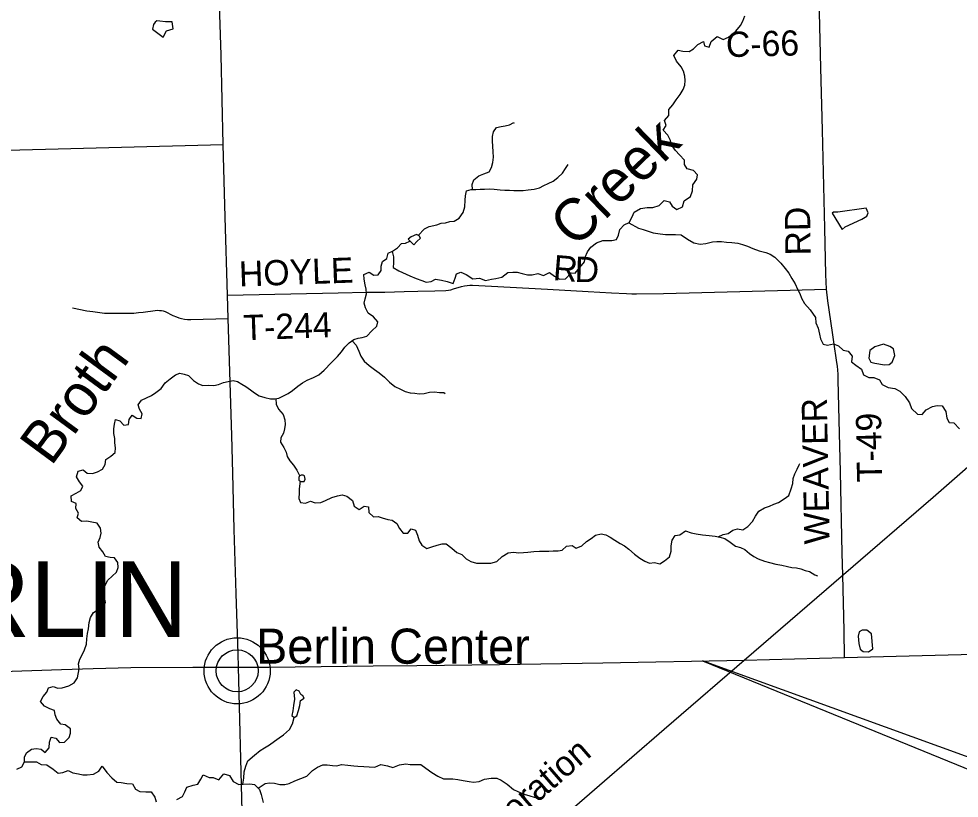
# Model space of a CAD drawing. Extents: x 0 to 34, y 0 to 22.
# Drawn here: x 4.591 to 6.707, y 17.274 to 19.028 of the extents above; entities that cross this region are included whole.
import ezdxf

# ---------------------------------------------------------------- set-up
doc = ezdxf.new("R2010")
doc.units = 0
for name, color, linetype in [('GM_X_County_Road_Text', 7, 'Continuous'), ('GM_X_Minor_Lake', 7, 'Continuous'), ('GM_X_Minor_River', 7, 'Continuous'), ('GM_X_Minor_River_Text', 7, 'Continuous'), ('GM_X_Rail_Line', 7, 'Continuous'), ('GM_X_Rail_Line_Text', 7, 'Continuous'), ('GM_X_State_Route', 7, 'Continuous'), ('GM_X_Township_Road', 7, 'Continuous'), ('GM_X_Township_Road_Text', 7, 'Continuous'), ('GM_X_Township_Text', 7, 'Continuous'), ('GM_X_Unincorporated', 7, 'Continuous'), ('GM_X_Unincorporated_Location', 7, 'Continuous'), ('GM_X_Unincorporated_Text', 7, 'Continuous'), ('GM_X_US_Route', 7, 'Continuous'), ('SH_Text', 7, 'Continuous')]:
    doc.layers.add(name, color=color, linetype=linetype)

msp = doc.modelspace()

# ---------------------------------------------------------------- linework, layer by layer
at = {"layer": 'GM_X_Minor_Lake'}
for points in [[(4.9357, 19.0214), (4.9205, 19.0217), (4.9076, 19.0231), (4.9015, 19.0234), (4.8973, 19.0204), (4.894, 19.0158), (4.8914, 19.0051), (4.9151, 18.9871), (4.923, 19.0016), (4.9382, 19.0059)], [(4.9382, 19.0059), (4.9357, 19.0214)], [(6.4435, 18.554), (6.4499, 18.5598), (6.4877, 18.5773), (6.499, 18.5843), (6.5016, 18.5916), (6.4977, 18.6018), (6.4335, 18.593), (6.424, 18.5933), (6.4206, 18.5909)], [(6.4206, 18.5909), (6.4435, 18.554)], [(5.4792, 18.5196), (5.486, 18.5269), (5.4943, 18.5345), (5.4915, 18.5394), (5.4854, 18.5428), (5.4737, 18.5374), (5.4669, 18.532)], [(5.4669, 18.532), (5.4792, 18.5196)], [(6.5385, 18.249), (6.5495, 18.2503), (6.5559, 18.2553), (6.5622, 18.2706), (6.5593, 18.285), (6.5509, 18.2906), (6.5364, 18.2958), (6.5167, 18.2898), (6.5058, 18.2817), (6.5033, 18.2642), (6.5076, 18.2555), (6.5168, 18.2529)], [(6.5168, 18.2529), (6.5385, 18.249)], [(5.2316, 18.0002), (5.2302, 18.001), (5.2299, 18.001), (5.2278, 18.001), (5.2256, 18.0009), (5.2233, 17.9998), (5.2216, 17.9979), (5.2207, 17.9957), (5.2205, 17.9932), (5.2206, 17.9898)], [(5.2206, 17.9898), (5.2252, 17.9865), (5.2325, 17.9869), (5.2351, 17.9922), (5.2335, 17.9991), (5.2316, 18.0002)], [(6.5097, 17.6441), (6.499, 17.6519), (6.4887, 17.6522), (6.4815, 17.6479), (6.4794, 17.6384), (6.4807, 17.622), (6.4839, 17.6095), (6.4905, 17.6039), (6.5027, 17.6029), (6.5128, 17.6099)], [(6.5128, 17.6099), (6.5097, 17.6441)], [(5.2053, 17.4597), (5.21, 17.4557), (5.2163, 17.4589), (5.2202, 17.4715), (5.223, 17.4822), (5.2243, 17.4937), (5.2325, 17.4992), (5.2297, 17.5044), (5.2251, 17.5074), (5.2215, 17.5149), (5.215, 17.5174), (5.2098, 17.5123), (5.2109, 17.4964), (5.2089, 17.4826), (5.2073, 17.4701)], [(5.2073, 17.4701), (5.2053, 17.4597)]]:
    msp.add_lwpolyline(points, dxfattribs=at)
at = {"layer": 'GM_X_Minor_River'}
for points in [[(6.134, 18.9673), (6.144, 18.9645), (6.149, 18.9776), (6.162, 18.9885), (6.1759, 18.982), (6.1879, 18.9872), (6.204, 19.0005), (6.2147, 19.0133), (6.2202, 19.0229), (6.2245, 19.0348)], [(5.4311, 18.5048), (5.4338, 18.4928), (5.4337, 18.4791), (5.4332, 18.4688), (5.4459, 18.4611), (5.4705, 18.4495), (5.4844, 18.4438), (5.4974, 18.4391), (5.5074, 18.4356), (5.5184, 18.4366), (5.5285, 18.4425), (5.5415, 18.4402), (5.5545, 18.4371), (5.5679, 18.4321), (5.5722, 18.4443), (5.5754, 18.4539), (5.5852, 18.4576), (5.5971, 18.4525), (5.6122, 18.443), (5.6274, 18.4445), (5.6408, 18.4395), (5.6541, 18.4424), (5.6639, 18.4438), (5.6779, 18.4464), (5.691, 18.4574), (5.7024, 18.458), (5.7119, 18.4579), (5.723, 18.4551), (5.7352, 18.452), (5.7455, 18.4522), (5.7584, 18.4552), (5.7714, 18.4505), (5.7846, 18.4569), (5.7962, 18.4492), (5.8081, 18.4419), (5.821, 18.4433), (5.8333, 18.4562), (5.8428, 18.456), (5.8532, 18.4684), (5.8639, 18.4812), (5.8648, 18.4915), (5.8706, 18.5038), (5.878, 18.5142), (5.8907, 18.5237), (5.9046, 18.5289), (5.9149, 18.5292), (5.9248, 18.529), (5.9354, 18.5312), (5.9401, 18.5415), (5.9428, 18.5542), (5.9525, 18.5646), (5.9642, 18.5695), (5.9707, 18.5822), (5.9754, 18.5929), (5.9893, 18.6016), (6.0048, 18.6039), (6.0177, 18.6038), (6.0317, 18.6083), (6.0429, 18.6192), (6.0551, 18.6161), (6.0607, 18.6063), (6.0715, 18.599), (6.0843, 18.6054), (6.0881, 18.6188), (6.1024, 18.6282), (6.107, 18.6413), (6.1071, 18.6546), (6.1167, 18.6673), (6.1176, 18.6769), (6.109, 18.6869), (6.0948, 18.6904), (6.0889, 18.7005), (6.0883, 18.71), (6.077, 18.7219), (6.0684, 18.7316), (6.0593, 18.7443), (6.0572, 18.7545), (6.0508, 18.7662), (6.0403, 18.7773), (6.0477, 18.7881), (6.0436, 18.7994), (6.0536, 18.8103), (6.0537, 18.8244), (6.0622, 18.8349), (6.0699, 18.8457), (6.0788, 18.8577), (6.0857, 18.8692), (6.0893, 18.8792), (6.0902, 18.8891), (6.0892, 18.899), (6.0863, 18.9103), (6.0811, 18.9205), (6.0709, 18.9328), (6.0649, 18.9455), (6.0741, 18.9576), (6.0852, 18.9555), (6.0989, 18.9547), (6.1091, 18.961), (6.1187, 18.9708), (6.1315, 18.9775), (6.134, 18.9673)], [(5.6117, 18.644), (5.6111, 18.6552), (5.6144, 18.6655), (5.6261, 18.6751), (5.6371, 18.679), (5.6489, 18.6837), (5.6545, 18.6936), (5.6574, 18.705), (5.6589, 18.7168), (5.658, 18.7286), (5.6575, 18.7415), (5.6566, 18.7525), (5.6562, 18.7632), (5.6587, 18.7738), (5.6655, 18.7834), (5.6757, 18.7858), (5.6852, 18.7874), (5.6947, 18.7897), (5.7046, 18.7947), (5.7053, 18.7936)], [(5.4892, 18.5408), (5.5032, 18.5555), (5.5142, 18.5605), (5.5313, 18.5645), (5.5407, 18.568), (5.551, 18.5692), (5.5605, 18.5719), (5.57, 18.5728), (5.5813, 18.5793), (5.5907, 18.592), (5.5944, 18.6053), (5.5947, 18.6197), (5.5961, 18.6296), (5.5983, 18.6411), (5.6082, 18.6438), (5.6188, 18.6443), (5.6291, 18.6447), (5.6386, 18.6448), (5.6492, 18.6453), (5.6603, 18.6446), (5.6736, 18.6432), (5.6846, 18.6429), (5.6949, 18.6422), (5.7048, 18.6419), (5.7154, 18.642), (5.7257, 18.6417), (5.7367, 18.6433), (5.75, 18.6446), (5.7622, 18.6481), (5.772, 18.6528), (5.7819, 18.6574), (5.7928, 18.6628), (5.8038, 18.6709), (5.8144, 18.6808), (5.8211, 18.6912), (5.8267, 18.7)], [(5.9632, 18.5691), (5.9854, 18.5571), (5.9953, 18.5539), (6.0065, 18.5499), (6.0183, 18.5464), (6.0336, 18.5441), (6.0458, 18.5429), (6.0584, 18.5428), (6.0682, 18.543), (6.0812, 18.5422), (6.0955, 18.5323), (6.1094, 18.5242), (6.1239, 18.5211), (6.1368, 18.5222), (6.1516, 18.5264), (6.1614, 18.5273), (6.1717, 18.5272), (6.1828, 18.5256), (6.195, 18.5251), (6.2087, 18.5231), (6.2194, 18.5203), (6.2301, 18.5168), (6.2424, 18.5114), (6.257, 18.506), (6.2716, 18.5022), (6.2812, 18.4982), (6.292, 18.492), (6.3056, 18.4783), (6.315, 18.4663), (6.3232, 18.4555), (6.3304, 18.4439), (6.3375, 18.4315), (6.3431, 18.4194), (6.3479, 18.4097), (6.3523, 18.3995), (6.3587, 18.3871), (6.3716, 18.3734), (6.3834, 18.3558), (6.3844, 18.3436), (6.3893, 18.3316), (6.3926, 18.3187), (6.3944, 18.3081), (6.4008, 18.2957), (6.4107, 18.2933), (6.424, 18.2966), (6.4355, 18.292), (6.446, 18.2823), (6.4567, 18.2799), (6.4661, 18.2687), (6.4641, 18.2561), (6.4742, 18.2484), (6.4869, 18.2396), (6.4918, 18.2268), (6.5037, 18.2206), (6.5144, 18.2212), (6.5274, 18.2154), (6.5338, 18.2049), (6.5472, 18.1984), (6.5621, 18.1957), (6.5729, 18.1899), (6.5854, 18.178), (6.5948, 18.1638), (6.5997, 18.1513), (6.6129, 18.138), (6.6232, 18.1378), (6.6325, 18.1479), (6.6464, 18.1555), (6.6573, 18.158), (6.6684, 18.1571), (6.6767, 18.1444), (6.6789, 18.1296), (6.6841, 18.1199), (6.6948, 18.1186), (6.7073, 18.1056)], [(5.0293, 18.203), (5.04, 18.205), (5.051, 18.2093), (5.062, 18.212), (5.0726, 18.214), (5.0825, 18.2118), (5.0921, 18.2055), (5.1016, 18.2006), (5.1116, 18.1927), (5.1212, 18.1863), (5.1315, 18.1796), (5.1441, 18.1755), (5.1566, 18.1725), (5.1665, 18.1726), (5.176, 18.1742), (5.1965, 18.1846), (5.2063, 18.1912), (5.2188, 18.2012), (5.229, 18.2085), (5.2396, 18.215), (5.254, 18.2209), (5.2657, 18.227), (5.2778, 18.237), (5.2944, 18.2543), (5.3076, 18.2684), (5.3166, 18.2788), (5.3245, 18.2891), (5.3343, 18.2987), (5.3441, 18.3064), (5.354, 18.3095), (5.3635, 18.3111), (5.3737, 18.3142), (5.385, 18.3261), (5.3964, 18.3364), (5.3982, 18.3463), (5.3886, 18.3573), (5.3771, 18.3656), (5.3709, 18.3777), (5.3677, 18.3879), (5.3699, 18.3978), (5.3729, 18.4092), (5.3724, 18.4195), (5.3697, 18.4297), (5.3676, 18.4423), (5.3672, 18.4525), (5.3793, 18.4576), (5.3892, 18.4512), (5.3991, 18.452), (5.4059, 18.4616), (5.4058, 18.4711), (5.4088, 18.4817), (5.419, 18.4891), (5.4219, 18.5005), (5.4318, 18.5051), (5.4427, 18.5124), (5.4514, 18.5224), (5.4609, 18.5232), (5.4708, 18.5281)], [(5.3404, 18.3035), (5.3499, 18.2935), (5.3554, 18.2798), (5.3604, 18.2692), (5.3681, 18.2579), (5.3793, 18.2481), (5.3907, 18.2391), (5.4018, 18.2316), (5.4133, 18.2214), (5.4249, 18.2105), (5.4364, 18.2003), (5.4497, 18.1943), (5.4597, 18.1895), (5.4715, 18.1865), (5.4814, 18.1859), (5.4913, 18.184), (5.5031, 18.1845), (5.5148, 18.188), (5.5258, 18.1885), (5.5369, 18.1871), (5.5472, 18.1872), (5.5502, 18.1849)], [(4.6481, 17.4811), (4.6397, 17.4913), (4.6457, 17.5024), (4.6536, 17.5123), (4.6577, 17.5222), (4.6675, 17.525), (4.6786, 17.5217), (4.6881, 17.5221), (4.7029, 17.5268), (4.7154, 17.5334), (4.7229, 17.5444), (4.7265, 17.565), (4.7249, 17.576), (4.7278, 17.5871), (4.7338, 17.5981), (4.7383, 17.608), (4.7431, 17.6206), (4.7438, 17.6324), (4.7452, 17.6446), (4.747, 17.6553), (4.7492, 17.669), (4.7521, 17.6804), (4.7589, 17.6915), (4.7691, 17.6988), (4.7797, 17.7034), (4.7857, 17.7145), (4.7837, 17.7263), (4.7809, 17.7392), (4.7846, 17.7532), (4.7909, 17.7647), (4.8007, 17.7739), (4.8105, 17.7823), (4.8139, 17.7934), (4.8134, 17.804), (4.8057, 17.8146), (4.7962, 17.8157), (4.7859, 17.8179), (4.7793, 17.8281), (4.7716, 17.8387), (4.7689, 17.8501), (4.7733, 17.8604), (4.7755, 17.8703), (4.7743, 17.882), (4.767, 17.8926), (4.7548, 17.8952), (4.7434, 17.8974), (4.7319, 17.8965), (4.722, 17.9048), (4.7249, 17.9151), (4.7191, 17.9257), (4.7198, 17.9371), (4.7091, 17.9416), (4.7082, 17.9545), (4.7196, 17.9603), (4.7298, 17.9664), (4.7343, 17.9764), (4.7274, 17.9862), (4.7204, 17.9975), (4.7241, 18.0101), (4.7351, 18.0132), (4.7447, 18.0053), (4.7561, 18.005), (4.7675, 18.0086), (4.7785, 18.0147), (4.7852, 18.025), (4.7866, 18.0361), (4.7976, 18.0434), (4.8074, 18.0518), (4.8081, 18.0625), (4.8068, 18.0739), (4.8064, 18.0834), (4.804, 18.0944), (4.8043, 18.1054), (4.8061, 18.1161), (4.8079, 18.126), (4.8178, 18.1234), (4.8266, 18.1136), (4.8373, 18.1148), (4.8387, 18.1262), (4.8458, 18.1362), (4.8562, 18.1294), (4.8657, 18.1287), (4.8683, 18.1394), (4.8625, 18.1492), (4.8589, 18.1594), (4.8665, 18.1698), (4.8778, 18.1752), (4.8888, 18.1806), (4.899, 18.1871), (4.9111, 18.1964), (4.9201, 18.2086), (4.9311, 18.2178), (4.9432, 18.227), (4.953, 18.2305), (4.9629, 18.2287), (4.9725, 18.225), (4.984, 18.2144), (4.9951, 18.2069), (5.005, 18.2025), (5.0175, 18.2033), (5.0293, 18.203)], [(5.1687, 18.173), (5.1697, 18.1605), (5.1747, 18.1495), (5.1855, 18.1374), (5.189, 18.1253), (5.1899, 18.115), (5.1884, 18.1055), (5.1862, 18.0952), (5.1802, 18.0849), (5.1796, 18.075), (5.1869, 18.0629), (5.1919, 18.0531), (5.1943, 18.0432), (5.2001, 18.033), (5.2086, 18.0232), (5.2159, 18.0122), (5.2217, 18.002), (5.2234, 17.9998)], [(6.1647, 17.8621), (6.1757, 17.8674), (6.1867, 17.8698), (6.1973, 17.8774), (6.2079, 17.8798), (6.2197, 17.8776), (6.2314, 17.8857), (6.2416, 17.8968), (6.2487, 17.909), (6.2559, 17.9201), (6.2687, 17.9271), (6.2797, 17.9313), (6.29, 17.9356), (6.2998, 17.9395), (6.3127, 17.9479), (6.3233, 17.9549), (6.3285, 17.9701), (6.3322, 17.9823), (6.3328, 17.9933), (6.3369, 18.0036), (6.3418, 18.0143), (6.347, 18.0242), (6.3485, 18.0269)], [(5.2237, 17.9876), (5.2216, 17.9705), (5.2217, 17.961), (5.221, 17.9488), (5.2241, 17.9393), (5.2359, 17.9379), (5.2469, 17.9425), (5.2576, 17.9388), (5.2702, 17.9393), (5.2804, 17.944), (5.2948, 17.9505), (5.3077, 17.9548), (5.3183, 17.9564), (5.3286, 17.9539), (5.3412, 17.9437), (5.3452, 17.9312), (5.3563, 17.9237), (5.3676, 17.9314), (5.3775, 17.9299), (5.3784, 17.9166), (5.3891, 17.9072), (5.399, 17.9077), (5.4085, 17.9051), (5.4207, 17.901), (5.431, 17.9), (5.441, 17.8925), (5.4472, 17.8811), (5.4552, 17.8701), (5.4659, 17.8706), (5.4734, 17.8802), (5.483, 17.8768), (5.488, 17.8662), (5.4915, 17.853), (5.4977, 17.8431), (5.5088, 17.836), (5.5198, 17.8395), (5.5323, 17.8434), (5.5429, 17.8462), (5.5524, 17.8466), (5.5647, 17.8365), (5.5766, 17.8271), (5.5873, 17.8222), (5.5973, 17.8124), (5.608, 17.8064), (5.6205, 17.8027), (5.6308, 17.8028), (5.6415, 17.8025), (5.6525, 17.803), (5.6661, 17.8069), (5.6786, 17.818), (5.6915, 17.8261), (5.704, 17.8277), (5.7158, 17.8263), (5.7265, 17.8272), (5.736, 17.8273), (5.7493, 17.8289), (5.7622, 17.8297), (5.7835, 17.8299), (5.7934, 17.8308), (5.804, 17.8309), (5.8135, 17.8321), (5.8233, 17.8409), (5.8355, 17.8429), (5.845, 17.8369), (5.8576, 17.8419), (5.8681, 17.8515), (5.8783, 17.8585), (5.8885, 17.8658), (5.9014, 17.8689), (5.9117, 17.8667), (5.9213, 17.8615), (5.9316, 17.8547), (5.9435, 17.8472), (5.9534, 17.842), (5.9637, 17.8345), (5.976, 17.8232), (5.9883, 17.8141), (5.9997, 17.807), (6.0097, 17.8025), (6.0214, 17.8045), (6.0329, 17.8016), (6.0435, 17.8081), (6.0548, 17.817), (6.0589, 17.8296), (6.0588, 17.8417), (6.0609, 17.855), (6.0673, 17.865), (6.0779, 17.8666), (6.0908, 17.8758), (6.1034, 17.8713), (6.1152, 17.8692), (6.1289, 17.8666), (6.1438, 17.8652), (6.1575, 17.8638), (6.1685, 17.8612), (6.1792, 17.8587), (6.1914, 17.85), (6.2033, 17.8414), (6.2148, 17.8381), (6.2243, 17.8336), (6.235, 17.8249)], [(6.235, 17.8249), (6.2446, 17.8182), (6.2545, 17.8129), (6.269, 17.8073), (6.2797, 17.804), (6.2938, 17.8007), (6.3079, 17.7985), (6.3205, 17.7952), (6.3304, 17.793), (6.3403, 17.7927), (6.3506, 17.7901), (6.3605, 17.7864), (6.37, 17.7842), (6.3823, 17.7767), (6.388, 17.7745)], [(4.5859, 17.3388), (4.5972, 17.3446), (4.6036, 17.3553), (4.6035, 17.3663), (4.608, 17.3759), (4.6189, 17.3839), (4.6296, 17.3859), (4.6406, 17.3841), (4.6502, 17.3766), (4.6589, 17.3869), (4.6595, 17.3999), (4.6636, 17.4109), (4.6735, 17.4091), (4.6819, 17.3993), (4.693, 17.4001), (4.7039, 17.4101), (4.7069, 17.42), (4.7068, 17.4299), (4.6949, 17.4389), (4.6854, 17.4407), (4.6762, 17.4513), (4.6727, 17.4612), (4.671, 17.4714), (4.6604, 17.4751), (4.6481, 17.4811)], [(5.0947, 17.3054), (5.0967, 17.3192), (5.0976, 17.3329), (5.1018, 17.3459), (5.1057, 17.3582), (5.121, 17.3707), (5.1337, 17.3809), (5.1435, 17.3872), (5.1547, 17.3939), (5.1656, 17.4022), (5.1768, 17.41), (5.1865, 17.4167), (5.1996, 17.4284), (5.2065, 17.4415), (5.21, 17.4557)], [(4.6036, 17.3553), (4.6307, 17.3558), (4.6411, 17.3496), (4.6537, 17.3491), (4.668, 17.3388), (4.6788, 17.3299), (4.6894, 17.3313), (4.7015, 17.3358), (4.7123, 17.3307), (4.7249, 17.3287), (4.7348, 17.3267), (4.7447, 17.3262), (4.7588, 17.3276), (4.7704, 17.3344), (4.7781, 17.3459), (4.7887, 17.3317), (4.7996, 17.3198), (4.8109, 17.3098), (4.8208, 17.3093), (4.8334, 17.3069), (4.8467, 17.3061), (4.8535, 17.2941), (4.8631, 17.2886), (4.8761, 17.2882), (4.8883, 17.2877), (4.8965, 17.2761), (4.8998, 17.2659)], [(5.1292, 17.2962), (5.1446, 17.3066), (5.1548, 17.308), (5.1662, 17.3079), (5.1777, 17.3047), (5.1891, 17.3046), (5.199, 17.3071), (5.2118, 17.3128), (5.2253, 17.3184), (5.2385, 17.3233), (5.2515, 17.3361), (5.2624, 17.3436), (5.2748, 17.3488), (5.2847, 17.3491), (5.2965, 17.3475), (5.3064, 17.3469), (5.317, 17.3495), (5.3311, 17.3479), (5.3441, 17.3467), (5.3536, 17.3458), (5.367, 17.3449), (5.3792, 17.3441), (5.3914, 17.3436), (5.4049, 17.3496), (5.4202, 17.3466), (5.4321, 17.3427), (5.4475, 17.3487), (5.4616, 17.351), (5.4715, 17.3497), (5.4844, 17.3496), (5.4954, 17.3499), (5.5063, 17.341), (5.5198, 17.3318), (5.5333, 17.323), (5.546, 17.3176), (5.5567, 17.3171), (5.5673, 17.3173), (5.5788, 17.3157), (5.5902, 17.3137), (5.604, 17.3117), (5.6139, 17.3101), (5.6264, 17.3115), (5.6385, 17.3164), (5.6536, 17.319), (5.6666, 17.3185), (5.6762, 17.3142), (5.6897, 17.305), (5.7037, 17.2932), (5.7137, 17.2885), (5.7275, 17.2831), (5.7402, 17.2788), (5.7501, 17.276), (5.7597, 17.2736)], [(4.9461, 17.2708), (4.9592, 17.2776), (4.9639, 17.2883), (4.9686, 17.2987), (4.983, 17.3032), (4.9936, 17.3054), (4.9998, 17.3165), (5.0057, 17.3262), (5.0187, 17.32), (5.0282, 17.3206), (5.0405, 17.3152), (5.0516, 17.3284), (5.065, 17.3249), (5.0726, 17.3114), (5.0857, 17.3049), (5.0955, 17.3055), (5.1104, 17.3062), (5.1207, 17.3049), (5.132, 17.2934), (5.1356, 17.2821), (5.1406, 17.2643)]]:
    msp.add_lwpolyline(points, dxfattribs=at)
at = {"layer": 'GM_X_Rail_Line'}
msp.add_lwpolyline([(5.8073, 17.2253), (5.8974, 17.3034), (6.0426, 17.4289), (6.6479, 17.9515), (6.8284, 18.1087)], dxfattribs=at)
at = {"layer": 'GM_X_State_Route'}
for points in [[(5.0719, 18.0057), (5.0696, 18.0902), (5.0619, 18.3533), (5.0598, 18.4059), (5.0552, 18.5818), (5.0505, 18.745), (5.0459, 18.9465), (5.0415, 19.0842)], [(5.0847, 17.5684), (5.0838, 17.599), (5.08, 17.7346), (5.0754, 17.8783), (5.0719, 18.0057)], [(5.1103, 16.5663), (5.1099, 16.5961), (5.0847, 17.5684)]]:
    msp.add_lwpolyline(points, dxfattribs=at)
at = {"layer": 'GM_X_Township_Road'}
for points in [[(6.408, 18.4195), (6.4068, 18.4524), (6.4043, 18.5569), (6.3989, 18.7778), (6.3954, 18.9178), (6.3926, 19.0426), (6.3876, 19.2294), (6.383, 19.4112), (6.3765, 19.6635)], [(3.0395, 18.6946), (3.3635, 18.7014), (5.0505, 18.745)], [(5.0598, 18.4059), (5.3093, 18.4114), (5.3732, 18.4126), (5.4146, 18.4133), (5.4575, 18.4145), (5.4885, 18.4153), (5.5269, 18.4157), (5.5518, 18.4168), (5.5573, 18.4174), (5.5626, 18.4185), (5.5687, 18.4202), (5.5871, 18.4255), (5.5933, 18.4271), (5.5999, 18.4281), (5.6058, 18.4286), (5.6117, 18.4286), (5.6542, 18.4262), (5.7801, 18.4195), (5.8721, 18.4145), (5.9241, 18.4116), (5.9584, 18.4098), (5.9698, 18.4093), (5.9807, 18.409), (6.0412, 18.4098), (6.1275, 18.4123), (6.3262, 18.4174), (6.408, 18.4195)], [(6.4485, 17.5907), (6.4476, 17.6514), (6.4448, 17.7758), (6.4435, 17.8256), (6.4395, 18.0087), (6.4369, 18.1246), (6.4347, 18.2157), (6.4343, 18.2281), (6.4336, 18.2375), (6.4327, 18.2463), (6.4315, 18.2547), (6.4299, 18.2652), (6.4264, 18.2906), (6.4218, 18.3224), (6.4114, 18.3931), (6.408, 18.4195)], [(4.711, 18.3774), (4.7438, 18.3712), (4.757, 18.3693), (4.7729, 18.3671), (4.7833, 18.366), (4.795, 18.3654), (4.8088, 18.3653), (4.838, 18.3653), (4.8494, 18.366), (4.8602, 18.3668), (4.8707, 18.368), (4.8975, 18.3717), (4.9031, 18.3721), (4.9073, 18.372), (4.9116, 18.3716), (4.9154, 18.3706), (4.9196, 18.3694), (4.9372, 18.3607), (4.9455, 18.3572), (4.9509, 18.3551), (4.957, 18.3534), (4.9636, 18.352), (4.9699, 18.3511), (4.9773, 18.3511), (5.0619, 18.3533)]]:
    msp.add_lwpolyline(points, dxfattribs=at)
at = {"layer": 'GM_X_Unincorporated'}
for radius in [0.0744, 0.0472]:
    msp.add_circle((5.0819, 17.5605), radius, dxfattribs=at)
at = {"layer": 'GM_X_Unincorporated_Location'}
msp.add_line((5.0819, 17.5605), (5.0819, 17.5605), dxfattribs=at)
at = {"layer": 'GM_X_US_Route'}
for points in [[(5.486, 17.5725), (5.6721, 17.5744), (5.9049, 17.5783), (6.2235, 17.5848), (6.4485, 17.5907), (7.1191, 17.6075), (7.1293, 17.6073), (7.1366, 17.6069), (7.1443, 17.6061), (7.1511, 17.6052), (7.158, 17.6037), (7.1656, 17.6022), (7.178, 17.5993), (7.2115, 17.5908), (7.2535, 17.5802), (7.2753, 17.5759)], [(4.6866, 17.5634), (4.7582, 17.5657), (4.8429, 17.5677), (4.9822, 17.5687), (5.0847, 17.5684), (5.1543, 17.5688), (5.388, 17.5714), (5.486, 17.5725)], [(3.4145, 17.5268), (3.4274, 17.5272), (3.478, 17.5301), (3.5017, 17.5306), (3.6213, 17.5328), (3.877, 17.5372), (4.1307, 17.5455), (4.3745, 17.5533), (4.6866, 17.5634)]]:
    msp.add_lwpolyline(points, dxfattribs=at)
at = {"layer": 'SH_Text'}
msp.add_lwpolyline([(11.7478, 15.5458), (6.1293, 17.5829), (11.7478, 15.2891)], close=True, dxfattribs=at)

# ---------------------------------------------------------------- texts
at = {"layer": 'GM_X_County_Road_Text'}
msp.add_text('C-66', height=0.05682, rotation=1.3726, dxfattribs=at).set_placement((6.1825, 18.942))
at = {"layer": 'GM_X_Minor_River_Text'}
for s, rotation, p in [('Creek', 44.1241, (5.843, 18.51)), ('Broth', 53.6649, (4.6632, 18.0192))]:
    msp.add_text(s, height=0.09474, rotation=rotation, dxfattribs=at).set_placement(p)
at = {"layer": 'GM_X_Rail_Line_Text'}
msp.add_text('Corporation', height=0.056629, rotation=40.8766, dxfattribs=at).set_placement((5.5834, 17.1119))
at = {"layer": 'GM_X_Township_Road_Text'}
for s, height, rotation, p in [('RD', 0.05682, 90.9806, (6.3728, 18.496)), ('R', 0.0568, 355.2876, (5.7913, 18.4404)), ('HOYLE', 0.05682, 2.0275, (5.0869, 18.4255)), ('D', 0.0568, 358.0072, (5.8407, 18.4364)), ('T-244', 0.05682, 1.9653, (5.0969, 18.3046)), ('WEAVER', 0.05682, 91.1279, (6.4153, 17.846)), ('T-49', 0.05682, 91.0617, (6.5338, 17.9858))]:
    msp.add_text(s, height=height, rotation=rotation, dxfattribs=at).set_placement(p)
at = {"layer": 'GM_X_Township_Text'}
msp.add_text('BERLIN', height=0.17045, rotation=0, dxfattribs=at).set_placement((4.1472, 17.6368))
at = {"layer": 'GM_X_Unincorporated_Text'}
msp.add_text('Berlin Center', height=0.078977, rotation=0, dxfattribs=at).set_placement((5.1243, 17.5765))

doc.saveas('drawing.dxf')
